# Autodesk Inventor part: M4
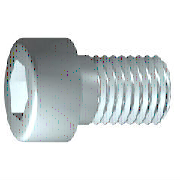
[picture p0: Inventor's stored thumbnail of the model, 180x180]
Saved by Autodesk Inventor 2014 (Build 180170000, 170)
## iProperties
IsCustomPart: 0
Created: 2016-04
Part Number: M4
Material: 강철, 연강
Description: 6각머리 태핑 나사
Document SubType Name: Modeling
Standard: KS B 1003
Designer: mdu
Standards Organization: KS
Language: ko-KR
Size Designation: M 4 x 10
Categories: <MemberInstance><Categories><Category DisplayName="조임쇠" InternalName="e4da775c-781d-43d5-af7c-5136215cf5a6" Mnemonic="FSTN"><Category DisplayName="볼트" InternalN
Density: 7.86 g/cm^3
Mass: 2.0371 g
Surface Area: 3.0572 cm^2
Volume: 0.259174 cm^3
Appearance: 금속 1800F 열
Author: mdu
Revision Number: 1
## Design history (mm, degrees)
sketch "스케치1"
  geometry: L1 (-1, 0)-(10, 0); L2 (10, 0)-(10, 2); L3 (10, 2)-(1.75, 2); L4 (1.75, 2)-(1.32, 2); L5 (1.32, 2)-(0, 2); L6 (0, 2)-(0, 3.5); L7 (0, 3.5)-(-4, 3.5); L8 (-4, 3.5)-(-4, 1.732); L9 (-4, 1.732)-(-2, 1.732); L10 (-2, 1.732)-(-1, 0); L11 (-6.8, 0)-(12.8, 0) reference; L12 (0, -0.7)-(0, 4.2) reference; L13 (1.75, 2)-(0, 2)
  constraints: 22 end point, 6 parallel, 2 collinear, 2 perpendicular, 1 horizontal, 1 point on line
  dimensions: "d1" = 8.25 distance from line of L3.end L2 (= GEL); "d2" = 0.42952 distance of L4.end L3.end (computed from GAL); "d3" = 4 distance between parallel lines of L8 L6 (= KOH); "d4" = 2 distance of L8.end L9.end (= INTI); "d5" = 60 deg angle of L10 L1; "d6" = 4 diameter of L3 L1 (= GD); "d7" = 4 diameter of L5 L1 (= BDM); "d8" = 3.4641 diameter of L9 L1 (= 1.1547 x SW); "d9" = 7 diameter of L7 L1 (= KOD); "d26" = 10 distance between parallel lines of L12 L2 (= NLG)
revolve "본체" sketch "스케치1" stored, may be unused: angle "d10" = 90 deg
sketch "스케치2"
  geometry: L1 (0, -4.9)-(0, 4.9) reference; L2 (-4.9, 0)-(4.9, 0) reference; L3 (1.732, 0)-(0.866, -1.5); L4 (0.866, -1.5)-(-0.866, -1.5); L5 (-0.866, -1.5)-(-1.732, 0); L6 (-1.732, 0)-(-0.866, 1.5); L7 (-0.866, 1.5)-(0.866, 1.5); L8 (0.866, 1.5)-(1.732, 0); 2 further points
  constraints: 12 end point, 1 coincident, 1 horizontal alignment, 1 point on line, 12 other
extrude "슬롯" join sketch "스케치2" stored distance "d11" = 10; taper "d12" = 0 deg
workplane "Work Plane1"
fillet "Fillet2" dims "d30" = 0.1 (= R)
body "Solid1"
fillet "모깎기1" dims "d17" = 0.4 (= RR)
feature "스레드" dims "d13" = 8.25 (= GEL), "d14" = 0
chamfer "모따기1" distance "d15" = 0.42941 (= -0.5 x SPD + 0.5 x GD); stored, may be unused: second distance "d16" = 0.42941 (= GUL), angle "d27" = 45 deg
other parameters: "GD" = 4 (= NND) [user parameter; used in 2 equation terms], "NLG" = 10 [user parameter; used in 1 equation term], "GEL" = 8.25 [user parameter; used in 2 equation terms], "KOD" = 7 [user parameter; used in 1 equation term], "KOH" = 4 [user parameter; used in 1 equation term], "INTI" = 2 [user parameter; used in 1 equation term], "GAL" = 0.42941 (= 0.61345 x PTC) [user parameter; used in 1 equation term], "GUL" = 0.42941 (= 0.61345 x PTC) [user parameter; used in 1 equation term], "BDM" = 4 (= NND) [user parameter; used in 1 equation term], "SW" = 3 [user parameter; used in 2 equation terms], "RR" = 0.4 [user parameter; used in 1 equation term], "SPD" = 3.14117 (= NND - 1.2269 x PTC) [user parameter; used in 1 equation term], "d19" = 0, "d28" = 0, "d29" = 0, "R" = 0.1 [user parameter; used in 1 equation term], "PHH" = 0.2 [user parameter], "GD1" = 3.14117 (= THREADDIA - 1.2269 x PTC) [user parameter], "THREADDIA" = 4 [user parameter; used in 1 equation term], "FAWI" = 45 deg [user parameter], "TPU" = 14.28571 (computed from PTC) [user parameter], "PTC" = 0.7 [user parameter; used in 5 equation terms], "NND" = 4 [user parameter; used in 3 equation terms], "TOA" = 30 deg [user parameter], "E0" = 3.465 (= 1.155 x SW) [user parameter]
